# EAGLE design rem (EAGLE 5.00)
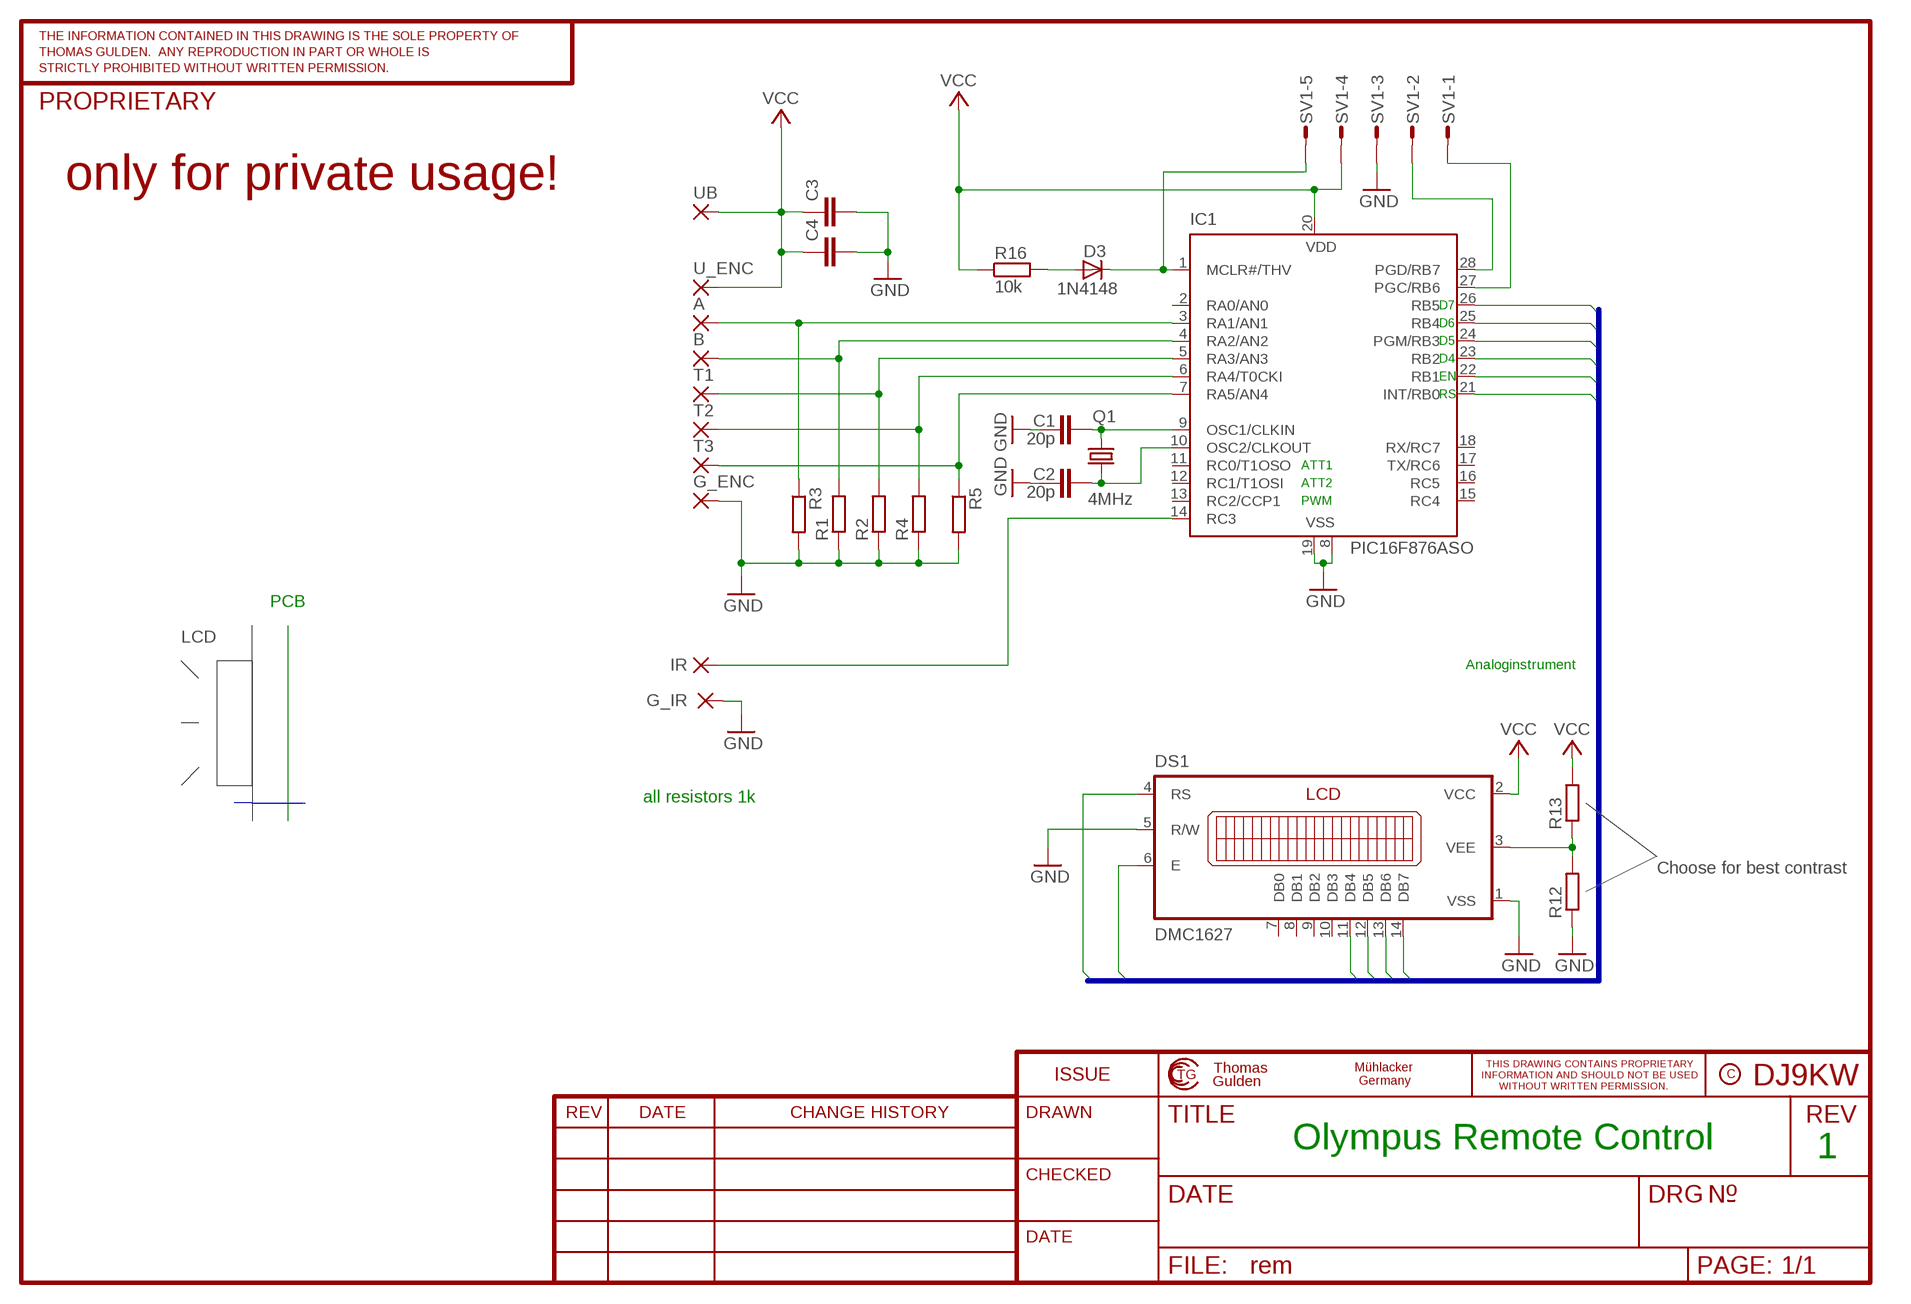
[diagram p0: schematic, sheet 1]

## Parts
A  2,54/0,8  [2,54/0,8]
B  2,54/0,8  [2,54/0,8]
C1  20p  C-EUC1206K  [C1206K]
C2  20p  C-EUC1206K  [C1206K]
C3  C-EUC0603K  [C0603K]
C4  C-EUC0603K  [C0603K]
D3  1N4148  DIODE-MELF-MLL41  [MELF-MLL41]
DS1  DMC1627  [DMC1627]
G_ENC  2,54/0,8  [2,54/0,8]
G_IR  PAD-0660-S  [0660-S]
IC1  PIC16F876ASO  PIC16F870SO  [SO-28W]
IR  PAD-0660-S  [0660-S]
Q1  4MHz  CRYTALHC49UP  [HC49UP]
R1  R-EU_R1206  [R1206]
R2  R-EU_R1206  [R1206]
R3  R-EU_R1206  [R1206]
R4  R-EU_R1206  [R1206]
R5  R-EU_R1206  [R1206]
R12  R-EU_M1206  [M1206]
R13  R-EU_M1206  [M1206]
R16  10k  R-EU_M1206  [M1206]
SV1  S05P  [S05P]
T1  2,54/0,8  [2,54/0,8]
T2  2,54/0,8  [2,54/0,8]
T3  2,54/0,8  [2,54/0,8]
U_ENC  2,54/0,8  [2,54/0,8]
UB  2,54/0,8  [2,54/0,8]

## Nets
CONTR: DS1.3(VEE) R12.2 R13.1
DB4: DS1.11(DB4) IC1.23(RB2)
DB5: DS1.12(DB5) IC1.24(PGM/RB3)
DB6: DS1.13(DB6) IC1.25(RB4)
DB7: DS1.14(DB7) IC1.26(RB5)
E: DS1.6(E) IC1.22(RB1)
GND: C1.1 C2.1 C3.2 C4.2 DS1.1(VSS) G_ENC.1(P) G_IR.P$1(P) IC1.8(VSS) IC1.19(VSS) R1.1 R2.1 R3.2 R4.1 R5.2 R12.1 SV1.3
N$1: A.1(P) IC1.3(RA1/AN1) R3.1
N$2: B.1(P) IC1.4(RA2/AN2) R1.2
N$3: IC1.5(RA3/AN3) R2.2 T1.1(P)
N$4: IC1.6(RA4/T0CKI) R4.2 T2.1(P)
N$5: IC1.14(RC3) IR.P$1(P)
N$6: IC1.7(RA5/AN4) R5.1 T3.1(P)
N$16: C1.2 IC1.9(OSC1/CLKIN) Q1.1
N$17: C2.2 IC1.10(OSC2/CLKOUT) Q1.2
N$21: IC1.27(PGC/RB6) SV1.1
N$22: D3.C IC1.1(MCLR#/THV) SV1.5
N$23: D3.A R16.2
N$25: IC1.28(PGD/RB7) SV1.2
RS: DS1.4(RS) IC1.21(INT/RB0)
RW: DS1.5(R/W) ; supply symbol labelled GND
VCC: C3.1 C4.1 DS1.2(VCC) IC1.20(VDD) R13.2 R16.1 SV1.4 U_ENC.1(P) UB.1(P)
Unconnected: DS1.7(DB0) DS1.8(DB1) DS1.9(DB2) DS1.10(DB3) IC1.2(RA0/AN0) IC1.11(RC0/T1OSO) IC1.12(RC1/T1OSI) IC1.13(RC2/CCP1) IC1.15(RC4) IC1.16(RC5) IC1.17(TX/RC6) IC1.18(RX/RC7)

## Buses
RS,E,DB4,DB5,DB6,DB7
B$1

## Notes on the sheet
- only for private usage!
- D7
- D6
- D5
- D4
- EN
- RS
- ATT1
- ATT2
- PWM
- PCB
- LCD
- Analoginstrument
- Component
- side
- all resistors 1k
- Choose for best contrast
- Olympus Remote Control | 1

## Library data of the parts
A B G_ENC T1-T3 U_ENC UB = wirepad:2,54/0,8: THROUGH-HOLE PAD
C1-C4 = rcl:C-EU: CAPACITOR, European symbol
D3 = diode:DIODE-: DIODE
DS1 = display-lcd:DMC1627: LCD DISPLAY Optrex, 16 characters x 2 Lines
G_IR IR = dpads:PAD: WIRE PAD
IC1 = microchip:PIC16*870: MICROCONTROLLER flash type
Q1 = crystal:CRYTAL: CRYSTAL
R1-R5 R12 R13 R16 = rcl:R-EU_: RESISTOR, European symbol
SV1 = con-amp-mt:S05P: AMP MT CONNECTOR

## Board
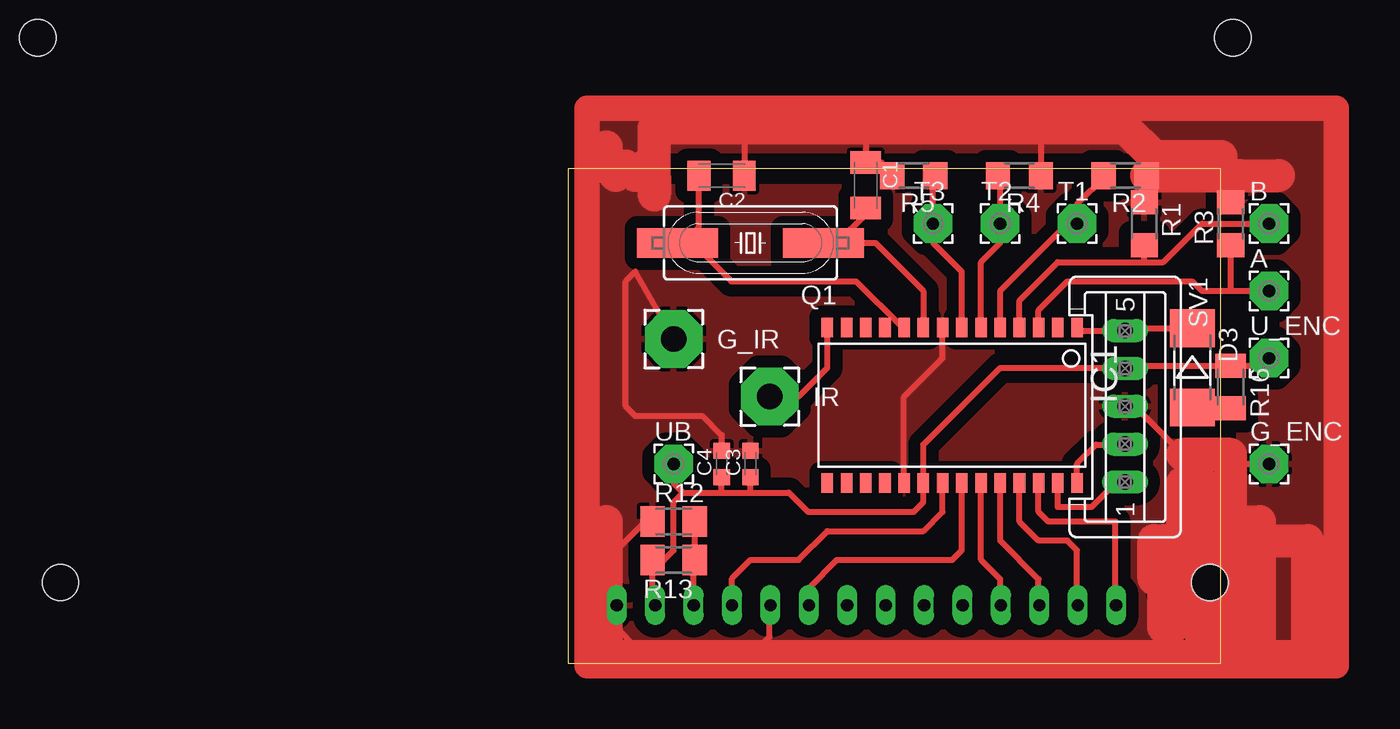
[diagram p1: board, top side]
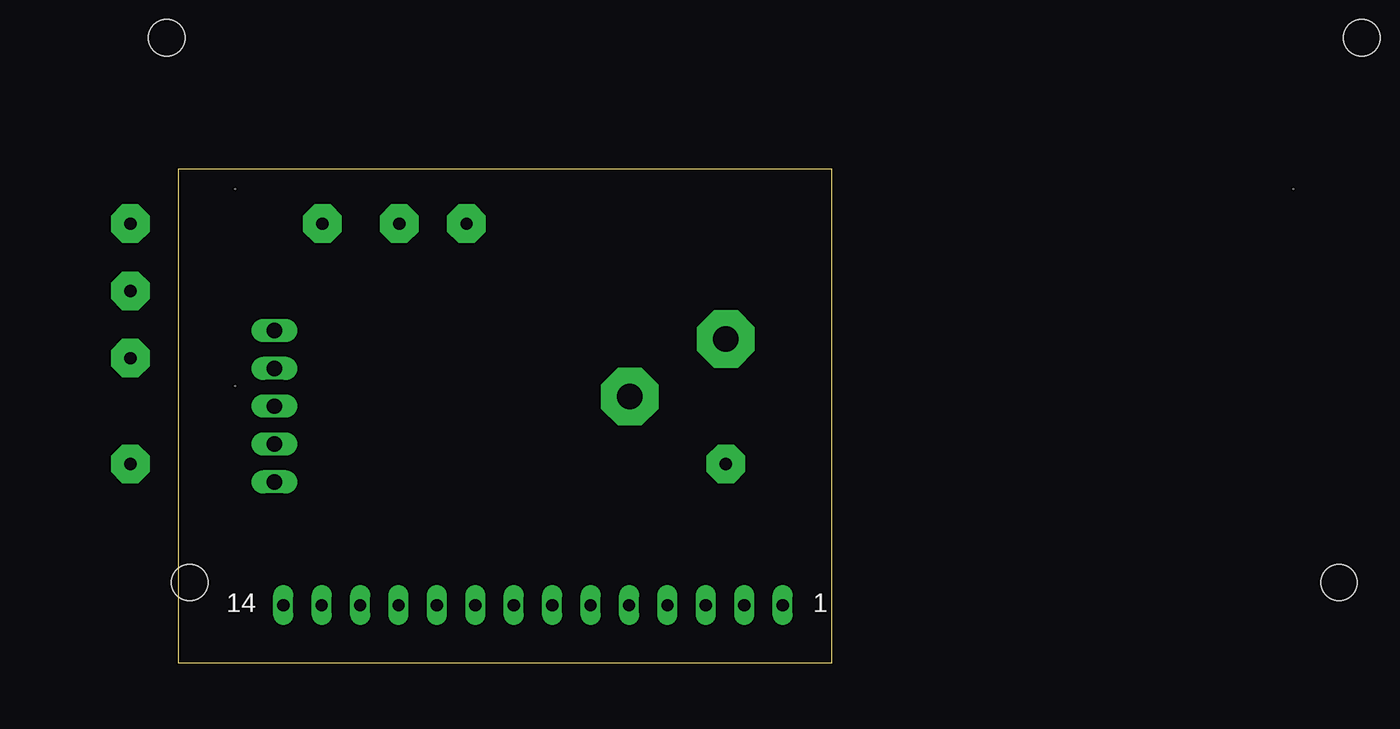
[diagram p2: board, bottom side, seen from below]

Size 43.16 x 32.69 mm. Coordinates in mm from the lower left corner, seen from the top.
Outline: 0,0 43.16,0 43.16,32.69 0,32.69 0,0
Copper layers (1*16): Top 0.035mm / dielectric 1.5mm / Bottom 0.035mm
Design rules "default": minimum track width 10mil, minimum drill 24mil, track to track 8mil, track to pad 8mil, pad to pad 8mil, via to via 8mil, smd to smd 8mil, copper to edge 40mil, drill to drill 8mil, minimum pad ring 10mil, minimum via ring 8mil, stop-mask expansion 4mil, vias tented up to drill 0mil, thermal gap 10mil

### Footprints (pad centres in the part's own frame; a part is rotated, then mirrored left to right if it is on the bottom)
2,54/0,8 = drill 0.813 pad 2.54 octagon: 1 0,0
C1206K = smd 1.5 x 2: 1 -1.5,0; 2 1.5,0
C0603K = smd 1.05 x 1.08: 1 -0.875,0; 2 0.875,0
MELF-MLL41 = smd 2.5 x 3: A 2.625,0; C -2.625,0
DMC1627 = drill 0.813 long: 1 1.22,-19.5; 2 -1.32,-19.5; 3 -3.86,-19.5; 4 -6.4,-19.5; 5 -8.94,-19.5; 6 -11.48,-19.5; 7 -14.02,-19.5; 8 -16.56,-19.5; 9 -19.1,-19.5; 10 -21.64,-19.5; 11 -24.18,-19.5; 12 -26.72,-19.5; 13 -29.26,-19.5; 14 -31.8,-19.5 | hole 2.4: -39.5,18; -38,-18; 38,-18; 39.5,18
0660-S = drill 1.676 pad 3.81 octagon: P$1 0,0
SO-28W = smd 0.762 x 1.27: 1 -7.62,-5.207; 2 -6.35,-5.207; 3 -5.08,-5.207; 4 -3.81,-5.207; 5 -2.54,-5.207; 6 -1.27,-5.207; 7 0,-5.207; 8 1.27,-5.207; 9 2.54,-5.207; 10 3.81,-5.207; 11 5.08,-5.207; 12 6.35,-5.207; 13 7.62,-5.207; 14 8.89,-5.207; 15 8.89,5.08; 16 7.62,5.08; 17 6.35,5.08; 18 5.08,5.08; 19 3.81,5.08; 20 2.54,5.08; 21 1.27,5.08; 22 0,5.08; 23 -1.27,5.08; 24 -2.54,5.08; 25 -3.81,5.08; 26 -5.08,5.08; 27 -6.35,5.08; 28 -7.62,5.08
HC49UP = smd 5.334 x 1.93: 1 -4.826,0; 2 4.826,0
R1206 = smd 1.6 x 1.803: 1 -1.422,0; 2 1.422,0
M1206 = smd 1.6 x 2: 1 -1.4,0; 2 1.4,0
S05P = drill 1.016 long: 1 5,0; 2 2.5,0; 3 0,0; 4 -2.5,0; 5 -5,0

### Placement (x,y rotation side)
A  46.35,24.6 0 top  (outside the outline)
B  46.35,29.05 0 top  (outside the outline)
C1  19.68,31.59 270 top
C2  10.16,32.22 180 top
C3  12.06,13.17 90 top
C4  10.16,13.17 90 top
D3  41.27,19.52 270 top
DS1  4.44,23.33 0 bottom
G_ENC  46.35,13.17 0 top  (outside the outline)
G_IR  6.98,21.42 0 top
IC1  26.03,16.98 180 top
IR  13.33,17.62 0 top
Q1  12.06,27.78 180 top
R1  38.09,29.05 270 top
R2  36.82,32.22 180 top
R3  43.81,29.05 90 top
R4  29.84,32.22 180 top
R5  22.85,32.22 180 top
R12  6.98,9.36 0 top
R13  6.98,6.82 180 top
R16  43.81,18.25 270 top
SV1  36.82,16.98 270 top
T1  33.65,29.05 0 top
T2  28.57,29.05 0 top
T3  24.12,29.05 0 top
U_ENC  46.35,20.16 0 top  (outside the outline)
UB  6.98,13.17 0 top

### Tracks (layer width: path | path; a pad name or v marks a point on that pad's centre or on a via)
CONTR
  Top 0.406: DS1.3 8.3,6.77 8.25,6.82 R13.1 8.38,9.23 8.25,9.36 R12.2
DB4
  Top 0.406: IC1.23 27.3,6.82 28.57,5.55 28.57,4.28 28.62,4.23 DS1.11
DB5
  Top 0.406: IC1.24 28.57,8.09 31.11,5.55 31.11,3.65 31.16,3.7 DS1.12
DB6
  Top 0.406: IC1.25 29.84,9.36 31.11,8.09 33.01,8.09 33.65,7.46 33.65,3.65 33.7,3.7 DS1.13
DB7
  Top 0.406: IC1.26 31.11,10 31.74,9.36 36.19,9.36 36.19,3.65 36.24,3.7 DS1.14
E
  Top 0.406: DS1.6 15.92,4.97 17.77,6.82 25.4,6.82 26.03,7.46 IC1.22
GND
  Top 0.406: R12.1 5.07,9.36 3.22,7.51 DS1.1 3.22,2.33 4.44,1.11 12.7,1.11 13.33,1.74 13.33,3.65 13.38,3.7 | SV1.3 37.46,16.98 40.63,13.81 41.27,13.17 G_ENC.1 | IC1.19 22.22,17.62 24.76,20.16 IC1.8 | C4.2 10.16,15.08 8.88,16.34 4.44,16.34 3.8,16.98 3.8,25.23 4.44,25.87 G_IR.P$1 | C2.1 11.66,36.44 11.42,36.67 | R5.2 21.59,32.22 20.72,33.09 C1.1 19.68,36.67 | R4.1 31.26,36.51 31.11,36.67 | R3.2 43.81,31.59 44.45,32.22 | R2.1 38.25,33.01 38.73,33.49
  Top 1.676: 1.27,-0.16 1.27,36.67 11.42,36.67 19.68,36.67 31.11,36.67 50.79,36.67 50.79,-0.16 1.27,-0.16
  Top 2.184: R2.1 44.45,32.22 46.98,32.22 | 43.18,13.81 40.63,13.81 43.81,13.81 43.81,1.74 45.71,1.74 45.71,9.36 42.54,9.36 42.54,10 41.9,10 41.9,11.9 40.63,11.9 40.63,6.82 40,6.82 40,2.38 39.37,2.38 39.37,8.09 38.73,8.09 38.73,5.55 41.9,5.55 | 41.9,5.55 41.9,8.09 48.89,8.09 48.89,1.74 49.52,1.74 49.52,1.11 50.16,1.11 50.16,0.47 2.53,0.47 | 2.53,0.47 2.53,9.36 | 2.53,0.47 41.9,0.47 41.9,5.55 | 1.9,32.86 1.9,33.49 2.53,34.12 2.53,32.86 3.17,32.22 3.8,32.86 4.44,32.22 5.07,32.86 5.71,32.22 5.71,31.59 | 5.71,31.59 5.71,30.95 | 5.71,31.59 5.71,35.4 36.82,35.4 38.73,33.49 43.18,33.49
  pour Top (isolate 0.813): 1.27,36.67 50.79,36.67 50.79,0.47 1.27,0.47
N$1
  Top 0.406: IC1.3 31.11,23.33 33.01,25.23 41.27,25.23 41.9,24.6 43.81,24.6 | 43.81,24.6 A.1 | 43.81,24.6 R3.1
N$2
  Top 0.406: IC1.4 29.84,23.97 32.38,26.51 38.09,26.51 | 38.09,26.51 39.37,26.51 41.9,29.05 B.1 | 38.09,26.51 R1.2
N$3
  Top 0.406: 28.57,22.06 IC1.5 28.57,24.6 33.01,29.05 T1.1 33.65,30.31 35.55,32.22 R2.2
N$4
  Top 0.406: 27.3,22.06 IC1.6 27.3,26.51 28.57,27.78 T2.1 28.57,32.22 R4.2
N$5
  Top 0.406: IR.P$1 15.23,17.62 17.14,19.52 IC1.14
N$6
  Top 0.406: IC1.7 26.03,25.87 24.12,27.78 T3.1 24.12,32.22 R5.1
N$16
  Top 0.406: 23.49,22.06 IC1.9 23.49,24.6 20.31,27.78 17.77,27.78 | Q1.1 17.77,27.78 | C1.2 19.68,29.68 17.77,27.78
N$17
  Top 0.406: 22.22,22.06 IC1.10 22.09,22.19 19.04,25.23 10.79,25.23 8.25,27.78 7.61,27.78 | Q1.2 7.61,27.78 | C2.2 8.66,28.81 7.61,27.78
N$21
  Top 0.406: IC1.27 32.38,10.63 32.38,10.31 34.6,10.31 36.19,11.9 36.82,11.9 SV1.1
N$22
  Top 0.406: IC1.1 33.65,22.06 33.73,21.98 SV1.5 36.82,22.06 36.91,22.15 D3.C
N$23
  Top 0.406: R16.2 43.18,16.98 43.09,16.9 D3.A
N$25
  Top 0.406: IC1.28 33.65,13.17 34.92,14.44 36.82,14.44 SV1.2
RS
  Top 0.406: DS1.4 10.84,5.6 12.06,6.82 15.23,6.82 17.14,8.73 23.49,8.73 24.76,10 IC1.21
VCC
  Top 0.406: 36.82,19.52 36.95,19.65 R16.1 46.35,19.65 U_ENC.1 | 36.82,19.52 SV1.4 | 36.82,19.52 28.57,19.52 23.49,14.44 IC1.20 23.49,10.63 22.85,10 15.87,10 14.6,11.27 12.06,11.27 | DS1.2 5.76,3.7 5.71,3.65 5.58,3.78 R13.2 6.34,6.82 6.98,7.46 6.98,10.63 7.61,11.27 | 7.61,11.27 10.16,11.27 | 10.16,11.27 12.06,11.27 | UB.1 6.98,11.9 7.61,11.27 | 10.16,11.27 C4.1 | 12.06,11.27 C3.1

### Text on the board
tValues: RS | RW | EN | DB4 | DB5 | DB6 | DB7 | GND | VCC | Contr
